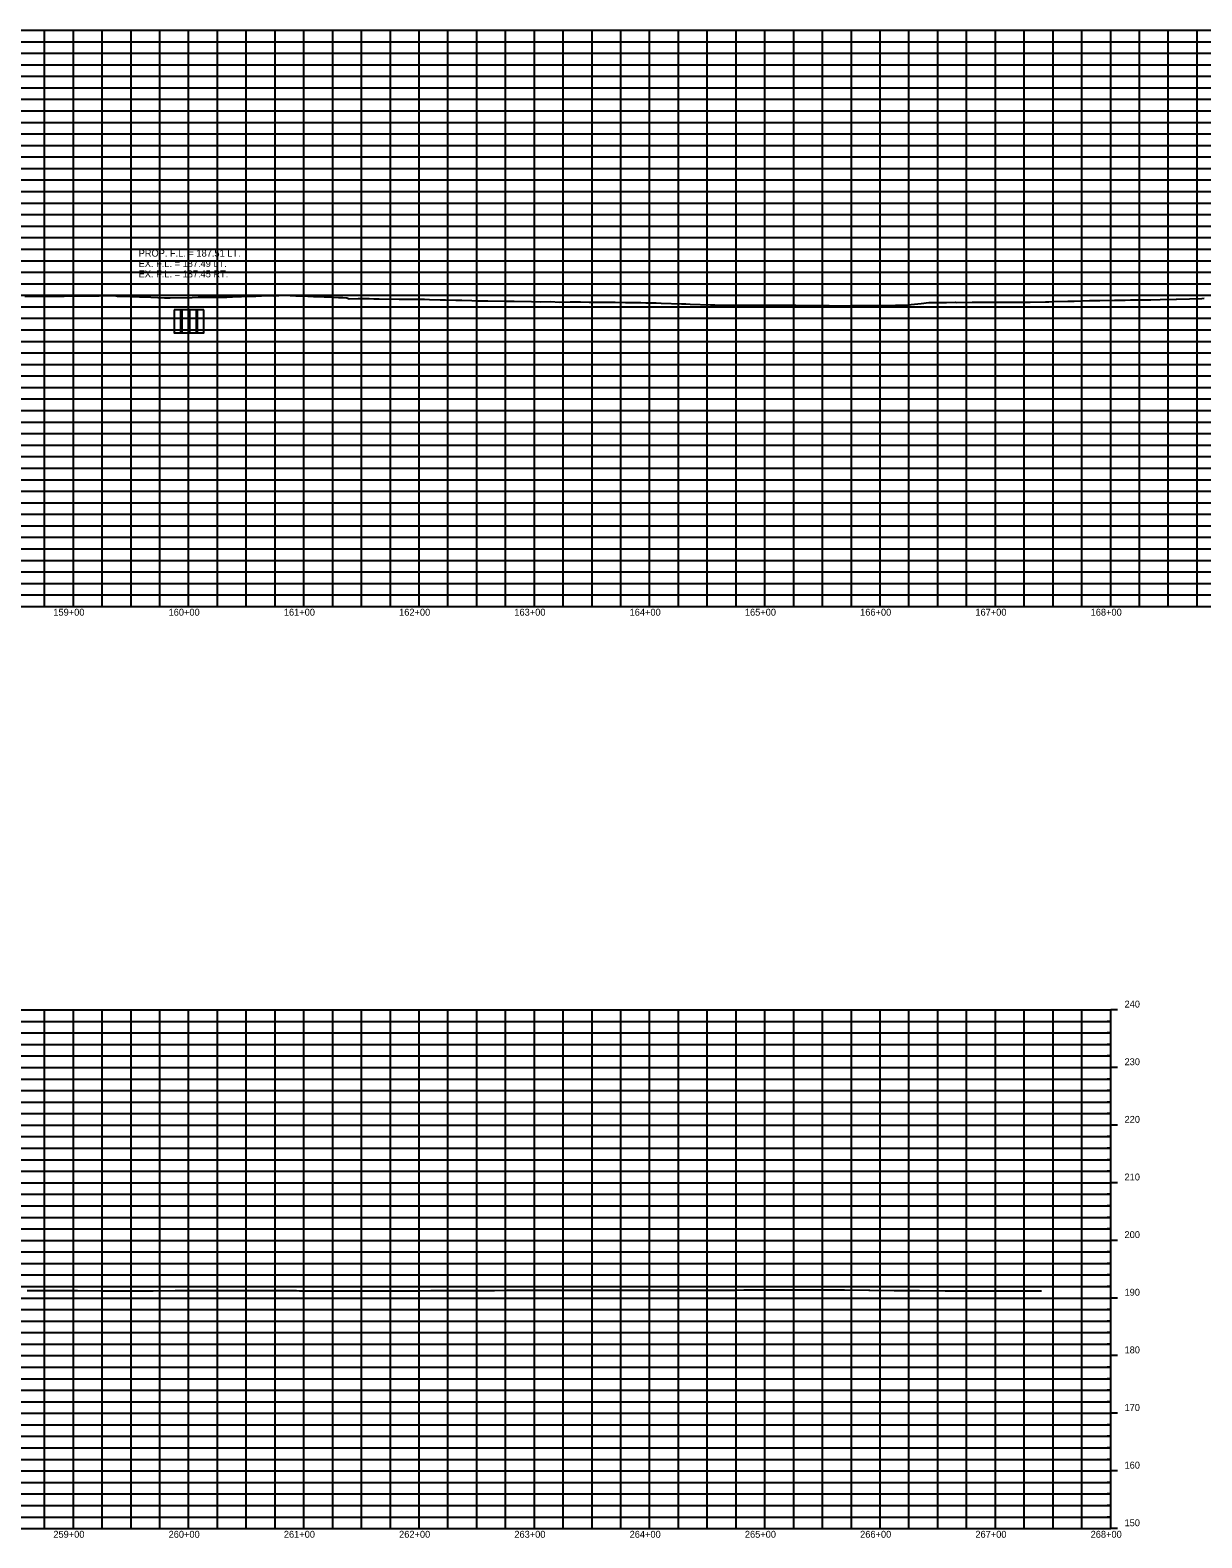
# Model space of a CAD drawing. Extents: x 1399671 to 1408349, y 1930471 to 1933387.
# Drawn here: x 1406187 to 1407203, y 1932071 to 1933379 of the extents above; entities that cross this region are included whole.
import ezdxf

# ---------------------------------------------------------------- set-up
doc = ezdxf.new("R2010")
doc.units = 0
for name, color, linetype in [('R_Drainage', 7, 'Continuous'), ('R_Exist Surface', 7, 'Continuous'), ('R_Grid', 7, 'Continuous'), ('R_Grid Annot', 7, 'Continuous'), ('R_Vert Alg Annot', 7, 'Continuous')]:
    doc.layers.add(name, color=color, linetype=linetype)

msp = doc.modelspace()

# ---------------------------------------------------------------- linework, layer by layer
at = {"layer": 'R_Drainage'}
for p, q in [((1406317.5, 1933136), (1406311.5, 1933136)), ((1406317.5, 1933116), (1406317.5, 1933136)), ((1406318.2, 1933136), (1406317.5, 1933136)), ((1406317.5, 1933136), (1406317.5, 1933116)), ((1406324.2, 1933136), (1406318.2, 1933136)), ((1406318.2, 1933136), (1406318.2, 1933116)), ((1406318.2, 1933116), (1406318.2, 1933136)), ((1406324.2, 1933116), (1406324.2, 1933136)), ((1406324.9, 1933136), (1406324.2, 1933136)), ((1406324.2, 1933136), (1406324.2, 1933116)), ((1406330.9, 1933136), (1406324.9, 1933136)), ((1406324.9, 1933136), (1406324.9, 1933116)), ((1406324.9, 1933116), (1406324.9, 1933136)), ((1406331.5, 1933136), (1406330.9, 1933136)), ((1406330.9, 1933136), (1406330.9, 1933116)), ((1406331.5, 1933116), (1406331.5, 1933136)), ((1406337.5, 1933136), (1406331.5, 1933136)), ((1406331.5, 1933136), (1406331.5, 1933116)), ((1406317.5, 1933116), (1406318.2, 1933116)), ((1406318.2, 1933116), (1406321.2, 1933116)), ((1406321.2, 1933116), (1406324.2, 1933116)), ((1406324.2, 1933116), (1406324.9, 1933116)), ((1406330.9, 1933116), (1406331.5, 1933116))]:
    msp.add_line(p, q, dxfattribs=at)
for points in [[(1406311.5, 1933136), (1406311.5, 1933116), (1406317.5, 1933116)], [(1406324.9, 1933116), (1406330.9, 1933116), (1406330.9, 1933136)], [(1406331.5, 1933116), (1406337.5, 1933116), (1406337.5, 1933136)]]:
    msp.add_lwpolyline(points, dxfattribs=at)
at = {"layer": 'R_Exist Surface'}
for points in [[(1406182, 1933147.7), (1406190.8, 1933147.7), (1406199.2, 1933147.7), (1406207.9, 1933147.7), (1406216.2, 1933147.9), (1406224.5, 1933148), (1406233.4, 1933148), (1406241.6, 1933148.2), (1406246.6, 1933148.2), (1406254.8, 1933148.3), (1406259.7, 1933148.4), (1406262.2, 1933147.7), (1406267.3, 1933147.7), (1406281.6, 1933147.1), (1406285.7, 1933147.2), (1406303.3, 1933146.3), (1406308.3, 1933146.4), (1406327.4, 1933146.7), (1406332.6, 1933146.8), (1406335.5, 1933146.8), (1406354.4, 1933147), (1406357.3, 1933147), (1406367.1, 1933147.4), (1406370, 1933147.4), (1406379.8, 1933147.9), (1406382.6, 1933147.9), (1406392.5, 1933148.3), (1406397.5, 1933148.2), (1406407.5, 1933148.7), (1406417.3, 1933148.2), (1406422.7, 1933148.1), (1406432.6, 1933147.6), (1406441.9, 1933147.1), (1406445.2, 1933147.1), (1406454.3, 1933146.6), (1406457.9, 1933146.6), (1406461.4, 1933146.5), (1406463.5, 1933145.4), (1406471.4, 1933145.8), (1406480.7, 1933145.7), (1406484.9, 1933145.6), (1406489.4, 1933145.4), (1406506.8, 1933145.3), (1406511.4, 1933145.2), (1406528.7, 1933145.1), (1406533.3, 1933144.9), (1406542.3, 1933144.7), (1406547.1, 1933144.6), (1406556, 1933144.4), (1406561.1, 1933144.2), (1406569.8, 1933144.1), (1406575.1, 1933143.9), (1406583.7, 1933143.7), (1406598.7, 1933143.5), (1406606.6, 1933143.4), (1406621.7, 1933143.2), (1406629.4, 1933143), (1406638.3, 1933143.1), (1406646.1, 1933142.7), (1406655.1, 1933142.8), (1406664.3, 1933142.9), (1406671.6, 1933142.6), (1406680.9, 1933142.7), (1406689.8, 1933142.7), (1406694.2, 1933142.5), (1406703.1, 1933142.4), (1406707.5, 1933142.2), (1406716.5, 1933142.2), (1406720.8, 1933142), (1406729.8, 1933141.9), (1406734.1, 1933141.8), (1406751.8, 1933141.3), (1406755.5, 1933141.1), (1406759.4, 1933140.8), (1406776.9, 1933140.4), (1406780.7, 1933140.2), (1406784.8, 1933139.9), (1406801, 1933140), (1406807.7, 1933140), (1406823.7, 1933140.1), (1406830.6, 1933140.1), (1406847, 1933139.9), (1406851.1, 1933139.9), (1406855.3, 1933139.8), (1406871.5, 1933139.7), (1406875.7, 1933139.6), (1406880, 1933139.6), (1406895.3, 1933139.4), (1406899.8, 1933139.6), (1406904.1, 1933139.8), (1406915.4, 1933139.7), (1406919.7, 1933139.6), (1406924, 1933139.8), (1406937.6, 1933140), (1406939.3, 1933140), (1406943.5, 1933140.1), (1406948.3, 1933140.2), (1406959.7, 1933141.5), (1406966.3, 1933142.3), (1406967.2, 1933142.4), (1406981.8, 1933142.4), (1406989.2, 1933142.5), (1406990.3, 1933142.4), (1407004, 1933142.5), (1407012.6, 1933142.6), (1407013.4, 1933142.6), (1407026.1, 1933142.6), (1407026.6, 1933142.6), (1407027.1, 1933142.6), (1407040.3, 1933142.7), (1407040.7, 1933142.7), (1407048.3, 1933142.7), (1407054, 1933142.7), (1407054.3, 1933142.7), (1407067.6, 1933142.8), (1407067.8, 1933142.8), (1407070.4, 1933142.9), (1407073.4, 1933143.1), (1407086.9, 1933143.5), (1407089.3, 1933143.6), (1407092.5, 1933143.6), (1407105.7, 1933144), (1407111.1, 1933144.1), (1407114.7, 1933144.1), (1407127.6, 1933144.3), (1407134.2, 1933144.4), (1407136.8, 1933144.4), (1407141.5, 1933144.5), (1407157.2, 1933144.7), (1407158.9, 1933144.7), (1407167, 1933144.9), (1407181.1, 1933145.3), (1407181.3, 1933145.3), (1407192.5, 1933145.6), (1407203.2, 1933145.9), (1407205.4, 1933146)], [(1406184, 1932285), (1406204.8, 1932285), (1406205.5, 1932285), (1406205.9, 1932285), (1406226.6, 1932285), (1406227.6, 1932285), (1406227.8, 1932285), (1406248.4, 1932284.9), (1406249.6, 1932284.9), (1406249.7, 1932284.9), (1406270.1, 1932284.9), (1406271.5, 1932284.9), (1406271.9, 1932284.9), (1406291.3, 1932284.9), (1406293.4, 1932284.9), (1406293.5, 1932284.9), (1406312.4, 1932285), (1406315.2, 1932285), (1406315.3, 1932285), (1406333, 1932285), (1406336.4, 1932285), (1406337.2, 1932285), (1406353.5, 1932285.1), (1406357.5, 1932285.1), (1406359.1, 1932285.1), (1406361.7, 1932285.1), (1406378.8, 1932285.1), (1406380.9, 1932285.1), (1406383.9, 1932285.1), (1406400, 1932285.1), (1406402.8, 1932285.1), (1406403.2, 1932285.1), (1406417.7, 1932285), (1406420.5, 1932284.9), (1406424.7, 1932284.9), (1406427.3, 1932284.9), (1406441.1, 1932284.8), (1406446.6, 1932284.8), (1406449, 1932284.8), (1406462.1, 1932284.8), (1406468.5, 1932284.8), (1406471.3, 1932284.8), (1406483.2, 1932284.8), (1406490.3, 1932284.8), (1406493.2, 1932284.8), (1406503.8, 1932284.8), (1406512.3, 1932284.9), (1406514.9, 1932284.9), (1406524.3, 1932284.9), (1406534.3, 1932285), (1406537.2, 1932285), (1406545.9, 1932285), (1406556.3, 1932285.1), (1406559.9, 1932285.1), (1406567.6, 1932285.2), (1406578.3, 1932285.2), (1406582.9, 1932285.2), (1406589.5, 1932285.2), (1406600.3, 1932285.3), (1406605.8, 1932285.3), (1406611.4, 1932285.3), (1406622.3, 1932285.3), (1406628.4, 1932285.3), (1406633.2, 1932285.3), (1406644.3, 1932285.4), (1406651, 1932285.4), (1406655, 1932285.4), (1406666.3, 1932285.4), (1406673.2, 1932285.5), (1406676.5, 1932285.5), (1406688.3, 1932285.5), (1406695.3, 1932285.5), (1406698.1, 1932285.5), (1406710.3, 1932285.5), (1406718, 1932285.4), (1406720.3, 1932285.4), (1406732.2, 1932285.4), (1406740.7, 1932285.3), (1406742.4, 1932285.3), (1406754.2, 1932285.3), (1406763.2, 1932285.3), (1406764.6, 1932285.3), (1406765.9, 1932285.3), (1406776.2, 1932285.3), (1406786.7, 1932285.4), (1406798.2, 1932285.5), (1406806, 1932285.6), (1406806.7, 1932285.6), (1406820.2, 1932285.7), (1406826.1, 1932285.8), (1406826.8, 1932285.8), (1406842.2, 1932285.8), (1406848, 1932285.8), (1406848.7, 1932285.8), (1406864.2, 1932285.8), (1406869.8, 1932285.8), (1406870.6, 1932285.8), (1406891.7, 1932285.6), (1406892.5, 1932285.6), (1406893.2, 1932285.6), (1406914.4, 1932285.4), (1406915.1, 1932285.4), (1406936.4, 1932285.2), (1406957.8, 1932285), (1406958.4, 1932285), (1406980.6, 1932284.9), (1406981.1, 1932284.9), (1406981.6, 1932284.9), (1407003.8, 1932284.9), (1407004.1, 1932284.9), (1407024.6, 1932284.8), (1407045.1, 1932284.8), (1407045.4, 1932284.8), (1407064.2, 1932284.8)]]:
    msp.add_lwpolyline(points, dxfattribs=at)
at = {"layer": 'R_Grid'}
for p, q in [((1400324.2, 1933378.6), (1408224.2, 1933378.6)), ((1400324.2, 1933378.6), (1408224.2, 1933378.6)), ((1406199.2, 1932878.6), (1406199.2, 1933378.6)), ((1406224.2, 1932878.6), (1406224.2, 1933378.6)), ((1406249.2, 1932878.6), (1406249.2, 1933378.6)), ((1406274.2, 1932878.6), (1406274.2, 1933378.6)), ((1406299.2, 1932878.6), (1406299.2, 1933378.6)), ((1406324.2, 1932878.6), (1406324.2, 1933378.6)), ((1406349.2, 1932878.6), (1406349.2, 1933378.6)), ((1406374.2, 1932878.6), (1406374.2, 1933378.6)), ((1406399.2, 1932878.6), (1406399.2, 1933378.6)), ((1406424.2, 1932878.6), (1406424.2, 1933378.6)), ((1406449.2, 1932878.6), (1406449.2, 1933378.6)), ((1406474.2, 1932878.6), (1406474.2, 1933378.6)), ((1406499.2, 1932878.6), (1406499.2, 1933378.6)), ((1406524.2, 1932878.6), (1406524.2, 1933378.6)), ((1406549.2, 1932878.6), (1406549.2, 1933378.6)), ((1406574.2, 1932878.6), (1406574.2, 1933378.6)), ((1406599.2, 1932878.6), (1406599.2, 1933378.6)), ((1406624.2, 1932878.6), (1406624.2, 1933378.6)), ((1406649.2, 1932878.6), (1406649.2, 1933378.6)), ((1406674.2, 1932878.6), (1406674.2, 1933378.6)), ((1406699.2, 1932878.6), (1406699.2, 1933378.6)), ((1406724.2, 1932878.6), (1406724.2, 1933378.6)), ((1406749.2, 1932878.6), (1406749.2, 1933378.6)), ((1406774.2, 1932878.6), (1406774.2, 1933378.6)), ((1406799.2, 1932878.6), (1406799.2, 1933378.6)), ((1406824.2, 1932878.6), (1406824.2, 1933378.6)), ((1406849.2, 1932878.6), (1406849.2, 1933378.6)), ((1406874.2, 1932878.6), (1406874.2, 1933378.6)), ((1406899.2, 1932878.6), (1406899.2, 1933378.6)), ((1406924.2, 1932878.6), (1406924.2, 1933378.6)), ((1406949.2, 1932878.6), (1406949.2, 1933378.6)), ((1406974.2, 1932878.6), (1406974.2, 1933378.6)), ((1406999.2, 1932878.6), (1406999.2, 1933378.6)), ((1407024.2, 1932878.6), (1407024.2, 1933378.6)), ((1407049.2, 1932878.6), (1407049.2, 1933378.6)), ((1407074.2, 1932878.6), (1407074.2, 1933378.6)), ((1407099.2, 1932878.6), (1407099.2, 1933378.6)), ((1407124.2, 1932878.6), (1407124.2, 1933378.6)), ((1407149.2, 1932878.6), (1407149.2, 1933378.6)), ((1407174.2, 1932878.6), (1407174.2, 1933378.6)), ((1407199.2, 1932878.6), (1407199.2, 1933378.6)), ((1400324.2, 1933368.6), (1408224.2, 1933368.6)), ((1400324.2, 1933358.6), (1408224.2, 1933358.6)), ((1400324.2, 1933348.6), (1408224.2, 1933348.6)), ((1400324.2, 1933338.6), (1408224.2, 1933338.6)), ((1400324.2, 1933328.6), (1408224.2, 1933328.6)), ((1400324.2, 1933318.6), (1408224.2, 1933318.6)), ((1400324.2, 1933308.6), (1408224.2, 1933308.6)), ((1400324.2, 1933298.6), (1408224.2, 1933298.6)), ((1400324.2, 1933288.6), (1408224.2, 1933288.6)), ((1400324.2, 1933278.6), (1408224.2, 1933278.6)), ((1400324.2, 1933268.6), (1408224.2, 1933268.6)), ((1400324.2, 1933258.6), (1408224.2, 1933258.6)), ((1400324.2, 1933248.6), (1408224.2, 1933248.6)), ((1400324.2, 1933238.6), (1408224.2, 1933238.6)), ((1400324.2, 1933228.6), (1408224.2, 1933228.6)), ((1400324.2, 1933218.6), (1408224.2, 1933218.6)), ((1400324.2, 1933208.6), (1408224.2, 1933208.6)), ((1400324.2, 1933198.6), (1408224.2, 1933198.6)), ((1400324.2, 1933188.6), (1408224.2, 1933188.6)), ((1400324.2, 1933178.6), (1408224.2, 1933178.6)), ((1400324.2, 1933168.6), (1408224.2, 1933168.6)), ((1400324.2, 1933158.6), (1408224.2, 1933158.6)), ((1400324.2, 1933148.6), (1408224.2, 1933148.6)), ((1400324.2, 1933138.6), (1408224.2, 1933138.6)), ((1400324.2, 1933128.6), (1408224.2, 1933128.6)), ((1400324.2, 1933118.6), (1408224.2, 1933118.6)), ((1400324.2, 1933108.6), (1408224.2, 1933108.6)), ((1400324.2, 1933098.6), (1408224.2, 1933098.6)), ((1400324.2, 1933088.6), (1408224.2, 1933088.6)), ((1400324.2, 1933078.6), (1408224.2, 1933078.6)), ((1400324.2, 1933068.6), (1408224.2, 1933068.6)), ((1400324.2, 1933058.6), (1408224.2, 1933058.6)), ((1400324.2, 1933048.6), (1408224.2, 1933048.6)), ((1400324.2, 1933038.6), (1408224.2, 1933038.6)), ((1400324.2, 1933028.6), (1408224.2, 1933028.6)), ((1400324.2, 1933018.6), (1408224.2, 1933018.6)), ((1400324.2, 1933008.6), (1408224.2, 1933008.6)), ((1400324.2, 1932998.6), (1408224.2, 1932998.6)), ((1400324.2, 1932988.6), (1408224.2, 1932988.6)), ((1400324.2, 1932978.6), (1408224.2, 1932978.6)), ((1400324.2, 1932968.6), (1408224.2, 1932968.6)), ((1400324.2, 1932958.6), (1408224.2, 1932958.6)), ((1400324.2, 1932948.6), (1408224.2, 1932948.6)), ((1400324.2, 1932938.6), (1408224.2, 1932938.6)), ((1400324.2, 1932928.6), (1408224.2, 1932928.6)), ((1400324.2, 1932918.6), (1408224.2, 1932918.6)), ((1400324.2, 1932908.6), (1408224.2, 1932908.6)), ((1400324.2, 1932898.6), (1408224.2, 1932898.6)), ((1400324.2, 1932888.6), (1408224.2, 1932888.6)), ((1400324.2, 1932878.6), (1408224.2, 1932878.6)), ((1400324.2, 1932528.6), (1407124.2, 1932528.6)), ((1400324.2, 1932528.6), (1407124.2, 1932528.6)), ((1406199.2, 1932078.6), (1406199.2, 1932528.6)), ((1406224.2, 1932078.6), (1406224.2, 1932528.6)), ((1406249.2, 1932078.6), (1406249.2, 1932528.6)), ((1406274.2, 1932078.6), (1406274.2, 1932528.6)), ((1406299.2, 1932078.6), (1406299.2, 1932528.6)), ((1406324.2, 1932078.6), (1406324.2, 1932528.6)), ((1406349.2, 1932078.6), (1406349.2, 1932528.6)), ((1406374.2, 1932078.6), (1406374.2, 1932528.6)), ((1406399.2, 1932078.6), (1406399.2, 1932528.6)), ((1406424.2, 1932078.6), (1406424.2, 1932528.6)), ((1406449.2, 1932078.6), (1406449.2, 1932528.6)), ((1406474.2, 1932078.6), (1406474.2, 1932528.6)), ((1406499.2, 1932078.6), (1406499.2, 1932528.6)), ((1406524.2, 1932078.6), (1406524.2, 1932528.6)), ((1406549.2, 1932078.6), (1406549.2, 1932528.6)), ((1406574.2, 1932078.6), (1406574.2, 1932528.6)), ((1406599.2, 1932078.6), (1406599.2, 1932528.6)), ((1406624.2, 1932078.6), (1406624.2, 1932528.6)), ((1406649.2, 1932078.6), (1406649.2, 1932528.6)), ((1406674.2, 1932078.6), (1406674.2, 1932528.6)), ((1406699.2, 1932078.6), (1406699.2, 1932528.6)), ((1406724.2, 1932078.6), (1406724.2, 1932528.6)), ((1406749.2, 1932078.6), (1406749.2, 1932528.6)), ((1406774.2, 1932078.6), (1406774.2, 1932528.6)), ((1406799.2, 1932078.6), (1406799.2, 1932528.6)), ((1406824.2, 1932078.6), (1406824.2, 1932528.6)), ((1406849.2, 1932078.6), (1406849.2, 1932528.6)), ((1406874.2, 1932078.6), (1406874.2, 1932528.6)), ((1406899.2, 1932078.6), (1406899.2, 1932528.6)), ((1406924.2, 1932078.6), (1406924.2, 1932528.6)), ((1406949.2, 1932078.6), (1406949.2, 1932528.6)), ((1406974.2, 1932078.6), (1406974.2, 1932528.6)), ((1406999.2, 1932078.6), (1406999.2, 1932528.6)), ((1407024.2, 1932078.6), (1407024.2, 1932528.6)), ((1407049.2, 1932078.6), (1407049.2, 1932528.6)), ((1407074.2, 1932078.6), (1407074.2, 1932528.6)), ((1407099.2, 1932078.6), (1407099.2, 1932528.6)), ((1407124.2, 1932078.6), (1407124.2, 1932528.6)), ((1400324.2, 1932518.6), (1407124.2, 1932518.6)), ((1400324.2, 1932508.6), (1407124.2, 1932508.6)), ((1400324.2, 1932498.6), (1407124.2, 1932498.6)), ((1400324.2, 1932488.6), (1407124.2, 1932488.6)), ((1400324.2, 1932478.6), (1407124.2, 1932478.6)), ((1400324.2, 1932468.6), (1407124.2, 1932468.6)), ((1400324.2, 1932458.6), (1407124.2, 1932458.6)), ((1400324.2, 1932448.6), (1407124.2, 1932448.6)), ((1400324.2, 1932438.6), (1407124.2, 1932438.6)), ((1400324.2, 1932428.6), (1407124.2, 1932428.6)), ((1400324.2, 1932418.6), (1407124.2, 1932418.6)), ((1400324.2, 1932408.6), (1407124.2, 1932408.6)), ((1400324.2, 1932398.6), (1407124.2, 1932398.6)), ((1400324.2, 1932388.6), (1407124.2, 1932388.6)), ((1400324.2, 1932378.6), (1407124.2, 1932378.6)), ((1400324.2, 1932368.6), (1407124.2, 1932368.6)), ((1400324.2, 1932358.6), (1407124.2, 1932358.6)), ((1400324.2, 1932348.6), (1407124.2, 1932348.6)), ((1400324.2, 1932338.6), (1407124.2, 1932338.6)), ((1400324.2, 1932328.6), (1407124.2, 1932328.6)), ((1400324.2, 1932318.6), (1407124.2, 1932318.6)), ((1400324.2, 1932308.6), (1407124.2, 1932308.6)), ((1400324.2, 1932298.6), (1407124.2, 1932298.6)), ((1400324.2, 1932288.6), (1407124.2, 1932288.6)), ((1400324.2, 1932278.6), (1407124.2, 1932278.6)), ((1400324.2, 1932268.6), (1407124.2, 1932268.6)), ((1400324.2, 1932258.6), (1407124.2, 1932258.6)), ((1400324.2, 1932248.6), (1407124.2, 1932248.6)), ((1400324.2, 1932238.6), (1407124.2, 1932238.6)), ((1400324.2, 1932228.6), (1407124.2, 1932228.6)), ((1400324.2, 1932218.6), (1407124.2, 1932218.6)), ((1400324.2, 1932208.6), (1407124.2, 1932208.6)), ((1400324.2, 1932198.6), (1407124.2, 1932198.6)), ((1400324.2, 1932188.6), (1407124.2, 1932188.6)), ((1400324.2, 1932178.6), (1407124.2, 1932178.6)), ((1400324.2, 1932168.6), (1407124.2, 1932168.6)), ((1400324.2, 1932158.6), (1407124.2, 1932158.6)), ((1400324.2, 1932148.6), (1407124.2, 1932148.6)), ((1400324.2, 1932138.6), (1407124.2, 1932138.6)), ((1400324.2, 1932128.6), (1407124.2, 1932128.6)), ((1400324.2, 1932118.6), (1407124.2, 1932118.6)), ((1400324.2, 1932108.6), (1407124.2, 1932108.6)), ((1400324.2, 1932098.6), (1407124.2, 1932098.6)), ((1400324.2, 1932088.6), (1407124.2, 1932088.6)), ((1400324.2, 1932078.6), (1407124.2, 1932078.6))]:
    msp.add_line(p, q, dxfattribs=at)
at = {"layer": 'R_Grid Annot'}
for p, q in [((1407130.2, 1932528.6), (1407124.2, 1932528.6)), ((1407130.2, 1932528.6), (1407124.2, 1932528.6)), ((1407124.2, 1932518.6), (1407121.2, 1932518.6)), ((1407124.2, 1932508.6), (1407121.2, 1932508.6)), ((1407124.2, 1932498.6), (1407121.2, 1932498.6)), ((1407124.2, 1932488.6), (1407121.2, 1932488.6)), ((1407130.2, 1932478.6), (1407124.2, 1932478.6)), ((1407124.2, 1932468.6), (1407121.2, 1932468.6)), ((1407124.2, 1932458.6), (1407121.2, 1932458.6)), ((1407124.2, 1932448.6), (1407121.2, 1932448.6)), ((1407124.2, 1932438.6), (1407121.2, 1932438.6)), ((1407130.2, 1932428.6), (1407124.2, 1932428.6)), ((1407124.2, 1932418.6), (1407121.2, 1932418.6)), ((1407124.2, 1932408.6), (1407121.2, 1932408.6)), ((1407124.2, 1932398.6), (1407121.2, 1932398.6)), ((1407124.2, 1932388.6), (1407121.2, 1932388.6)), ((1407130.2, 1932378.6), (1407124.2, 1932378.6)), ((1407124.2, 1932368.6), (1407121.2, 1932368.6)), ((1407124.2, 1932358.6), (1407121.2, 1932358.6)), ((1407124.2, 1932348.6), (1407121.2, 1932348.6)), ((1407124.2, 1932338.6), (1407121.2, 1932338.6)), ((1407124.2, 1932318.6), (1407121.2, 1932318.6)), ((1407130.2, 1932328.6), (1407124.2, 1932328.6)), ((1407124.2, 1932308.6), (1407121.2, 1932308.6)), ((1407124.2, 1932298.6), (1407121.2, 1932298.6)), ((1407124.2, 1932288.6), (1407121.2, 1932288.6)), ((1407130.2, 1932278.6), (1407124.2, 1932278.6)), ((1407124.2, 1932268.6), (1407121.2, 1932268.6)), ((1407124.2, 1932258.6), (1407121.2, 1932258.6)), ((1407124.2, 1932248.6), (1407121.2, 1932248.6)), ((1407124.2, 1932238.6), (1407121.2, 1932238.6)), ((1407130.2, 1932228.6), (1407124.2, 1932228.6)), ((1407124.2, 1932218.6), (1407121.2, 1932218.6)), ((1407124.2, 1932208.6), (1407121.2, 1932208.6)), ((1407124.2, 1932198.6), (1407121.2, 1932198.6)), ((1407124.2, 1932188.6), (1407121.2, 1932188.6)), ((1407130.2, 1932178.6), (1407124.2, 1932178.6)), ((1407124.2, 1932168.6), (1407121.2, 1932168.6)), ((1407124.2, 1932158.6), (1407121.2, 1932158.6)), ((1407124.2, 1932148.6), (1407121.2, 1932148.6)), ((1407124.2, 1932138.6), (1407121.2, 1932138.6)), ((1407130.2, 1932128.6), (1407124.2, 1932128.6)), ((1407124.2, 1932118.6), (1407121.2, 1932118.6)), ((1407124.2, 1932108.6), (1407121.2, 1932108.6)), ((1407124.2, 1932098.6), (1407121.2, 1932098.6)), ((1407124.2, 1932088.6), (1407121.2, 1932088.6)), ((1407130.2, 1932078.6), (1407124.2, 1932078.6))]:
    msp.add_line(p, q, dxfattribs=at)

# ---------------------------------------------------------------- texts
for s, p in [('159+00', (1406206.8, 1932870.6)), ('160+00', (1406306.8, 1932870.6)), ('161+00', (1406406.8, 1932870.6)), ('162+00', (1406506.8, 1932870.6)), ('163+00', (1406606.8, 1932870.6)), ('164+00', (1406706.8, 1932870.6)), ('165+00', (1406806.8, 1932870.6)), ('166+00', (1406906.8, 1932870.6)), ('167+00', (1407006.8, 1932870.6)), ('168+00', (1407106.8, 1932870.6)), ('240', (1407136.2, 1932530.6)), ('240', (1407136.2, 1932530.6)), ('230', (1407136.2, 1932480.6)), ('220', (1407136.2, 1932430.6)), ('210', (1407136.2, 1932380.6)), ('200', (1407136.2, 1932330.6)), ('190', (1407136.2, 1932280.6)), ('180', (1407136.2, 1932230.6)), ('170', (1407136.2, 1932180.6)), ('160', (1407136.2, 1932130.6)), ('150', (1407136.2, 1932080.6)), ('259+00', (1406206.8, 1932070.6)), ('260+00', (1406306.8, 1932070.6)), ('261+00', (1406406.8, 1932070.6)), ('262+00', (1406506.8, 1932070.6)), ('263+00', (1406606.8, 1932070.6)), ('264+00', (1406706.8, 1932070.6)), ('265+00', (1406806.8, 1932070.6)), ('266+00', (1406906.8, 1932070.6)), ('267+00', (1407006.8, 1932070.6)), ('268+00', (1407106.8, 1932070.6))]:
    msp.add_text(s, height=6, dxfattribs=at).set_placement(p)
at = {"layer": 'R_Vert Alg Annot'}
for s, p in [('PROP. F.L. = 187.51 LT.', (1406280.8, 1933182.1)), ('EX. F.L. = 187.49 LT.', (1406280.8, 1933173.1)), ('EX. F.L. = 187.45 RT.', (1406280.8, 1933164.1))]:
    msp.add_text(s, height=6, dxfattribs=at).set_placement(p)

doc.saveas('drawing.dxf')
